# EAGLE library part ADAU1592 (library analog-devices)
Class-D Audio Power Amplifier Source: http://www.analog.com/static/imported-files/data_sheets/ADAU1592.pdf
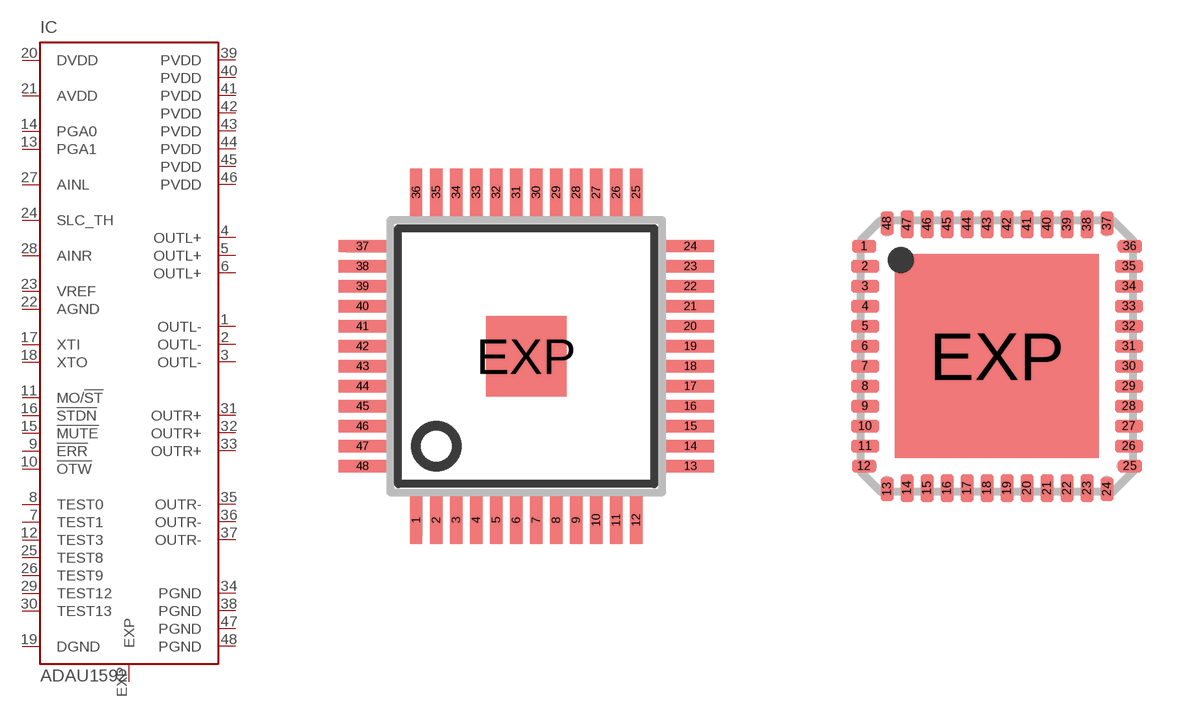
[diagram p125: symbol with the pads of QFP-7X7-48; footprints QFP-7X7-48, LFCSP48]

Designator prefix IC

## ADAU1592SV (OC_FARNELL: 1498683; OC_NEWARK: unknown)  [QFP-7X7-48]
1  OUTL-  pas
2  OUTL-  out
3  OUTL-  pas
4  OUTL+  pas
5  OUTL+  out
6  OUTL+  pas
7  TEST1  in
8  TEST0  in
9  !ERR  out
10  !OTW  out
11  MO/!ST  in
12  TEST3  in
13  PGA1  in
14  PGA0  in
15  !MUTE  in
16  !STDN  in
17  XTI  in
18  XTO  out
19  DGND  in
20  DVDD  in
21  AVDD  in
22  AGND  in
23  VREF  in
24  SLC_TH  in
25  TEST8  in
26  TEST9  in
27  AINL  in
28  AINR  in
29  TEST12  in
30  TEST13  in
31  OUTR+  pas
32  OUTR+  out
33  OUTR+  pas
34  PGND  in
35  OUTR-  pas
36  OUTR-  out
37  OUTR-  pas
38  PGND  in
39  PVDD  in
40  PVDD  in
41  PVDD  in
42  PVDD  in
43  PVDD  in
44  PVDD  in
45  PVDD  in
46  PVDD  in
47  PGND  in
48  PGND  in
EXP  EXP  pas

## ADAU1592CP (MPN: ADAU1592ACPZ; OC_FARNELL: 1498683; OC_NEWARK: 50M0756)  [LFCSP48]
Pads as for QFP-7X7-48

## Footprint QFP-7X7-48 (pad centres in mm)
TQFP48 7x7 Thin Plastic Quad Flat Package, Exposed Pad, TQFP/EP Source: www.analog.com/UploadedFiles/Data_Sheets/33830397585263AD9859_0.pdf
smd 0.3 x 1.2: 1 -2.75,-4.1; 2 -2.25,-4.1; 3 -1.75,-4.1; 4 -1.25,-4.1; 5 -0.75,-4.1; 6 -0.25,-4.1; 7 0.25,-4.1; 8 0.75,-4.1; 9 1.25,-4.1; 10 1.75,-4.1; 11 2.25,-4.1; 12 2.75,-4.1; 25 2.75,4.1; 26 2.25,4.1; 27 1.75,4.1; 28 1.25,4.1; 29 0.75,4.1; 30 0.25,4.1; 31 -0.25,4.1; 32 -0.75,4.1; 33 -1.25,4.1; 34 -1.75,4.1; 35 -2.25,4.1; 36 -2.75,4.1
smd 1.2 x 0.3: 13 4.1,-2.75; 14 4.1,-2.25; 15 4.1,-1.75; 16 4.1,-1.25; 17 4.1,-0.75; 18 4.1,-0.25; 19 4.1,0.25; 20 4.1,0.75; 21 4.1,1.25; 22 4.1,1.75; 23 4.1,2.25; 24 4.1,2.75; 37 -4.1,2.75; 38 -4.1,2.25; 39 -4.1,1.75; 40 -4.1,1.25; 41 -4.1,0.75; 42 -4.1,0.25; 43 -4.1,-0.25; 44 -4.1,-0.75; 45 -4.1,-1.25; 46 -4.1,-1.75; 47 -4.1,-2.25; 48 -4.1,-2.75
smd 2 x 2: EXP 0,0

## Footprint LFCSP48 (pad centres in mm)
Lead Frame Chip Scale Package LFCSP CP-48 COMPLIANT TO JEDEC STANDARDS MO-220-VKKD-2 Source: http://www.analog.com/UploadedFiles/Data_Sheets/39780344872292AD7651_0.pdf
smd 0.6 x 0.32: 1 -3.325,2.75; 12 -3.325,-2.75; 25 3.325,-2.75; 36 3.325,2.75
smd 0.7 x 0.32: 2 -3.3,2.25; 3 -3.3,1.75; 4 -3.3,1.25; 5 -3.3,0.75; 6 -3.3,0.25; 7 -3.3,-0.25; 8 -3.3,-0.75; 9 -3.3,-1.25; 10 -3.3,-1.75; 11 -3.3,-2.25; 26 3.3,-2.25; 27 3.3,-1.75; 28 3.3,-1.25; 29 3.3,-0.75; 30 3.3,-0.25; 31 3.3,0.25; 32 3.3,0.75; 33 3.3,1.25; 34 3.3,1.75; 35 3.3,2.25
smd 0.32 x 0.6: 13 -2.75,-3.325; 24 2.75,-3.325; 37 2.75,3.325; 48 -2.75,3.325
smd 0.32 x 0.7: 14 -2.25,-3.3; 15 -1.75,-3.3; 16 -1.25,-3.3; 17 -0.75,-3.3; 18 -0.25,-3.3; 19 0.25,-3.3; 20 0.75,-3.3; 21 1.25,-3.3; 22 1.75,-3.3; 23 2.25,-3.3; 38 2.25,3.3; 39 1.75,3.3; 40 1.25,3.3; 41 0.75,3.3; 42 0.25,3.3; 43 -0.25,3.3; 44 -0.75,3.3; 45 -1.25,3.3; 46 -1.75,3.3; 47 -2.25,3.3
smd 5.1 x 5.1: EXP 0,0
